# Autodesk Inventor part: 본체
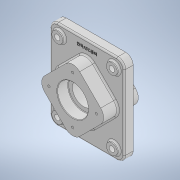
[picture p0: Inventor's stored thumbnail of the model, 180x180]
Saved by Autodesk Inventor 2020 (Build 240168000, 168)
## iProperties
Created: 2021-07
Part Number: 본체
Material: 일반
Document SubType Name: Modeling
Designer: Owner
Mass: 807.262 g
Surface Area: 966.427 cm^2
Volume: 807.262 cm^3
Density: 1 g/cm^3
Appearance: 기본값
Author: Owner
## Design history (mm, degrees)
sketch "스케치1"
  geometry: L1 (75, 90)-(-75, 90); L2 (-75, 90)-(-75, -90); L3 (-75, -90)-(75, -90); L4 (75, -90)-(75, 90); L5 (75, 90)-(-75, -90); L6 (-75, 90)-(75, -90); 1 further point
  constraints: 12 end point, 2 midpoint, 2 parallel, 1 horizontal, 1 perpendicular
  dimensions: "d0" = 150 distance of L3.end L2.end; "d1" = 180 distance of L2.end L1.end
extrude "돌출1" new body sketch "스케치1" stored distance "d2" = 18; taper "d3" = 0 deg
sketch "스케치2"
  geometry: L1 (0, -70.711)-(-70.711, 0); L2 (-70.711, 0)-(0, 70.711); L3 (0, 70.711)-(70.711, 0); L4 (70.711, 0)-(0, -70.711); L5 (0, -70.711)-(0, 70.711); L6 (-70.711, 0)-(70.711, 0); 2 further points
  constraints: 12 end point, 3 midpoint, 2 parallel, 1 horizontal alignment, 1 perpendicular, 1 vertical alignment
  dimensions: "d4" = 100 distance of L1.end L2.end
extrude "돌출2" join sketch "스케치2" distance "d5" = 29; taper "d6" = 0 deg
sketch "스케치3"
  geometry: L1 (0, 70.711)-(-70.711, 0) reference; L2 (70.711, 0)-(0, 70.711) reference; L3 (-70.711, 0)-(0, -70.711) reference; L4 (0, -70.711)-(70.711, 0) reference; L5 (-75, -90)-(75, -90) reference; L6 (75, -90)-(75, 90) reference; L7 (75, 90)-(-75, 90) reference; L8 (-75, 90)-(-75, -90) reference; 1 further point
extrude "돌출3" join sketch "스케치3" distance "d7" = 23; taper "d8" = 0 deg
fillet "모깎기1" dims "d9" = 20
fillet "모깎기2" dims "d10" = 20
sketch "스케치4"
  geometry: 2 further points
  constraints: 1 vertical alignment
  dimensions: "d11" = 48 distance of point (0, 0) point (0, 48)
hole "구멍1" sketch "스케치4" at (0, 48) diameter "d12" = 4.917; stored, may be unused: countersink angle "d16" = 90 deg, drill point angle "d18" = 118 deg; dims "d13" = 10, "d14" = 4, "d15" = 2, "d17" = 13
sketch "스케치5"
  geometry: C1 r 31 at (0, 0); 1 further point
  constraints: 1 centre point, 1 coincident
  dimensions: "d19" = 62 diameter of C1
extrude "돌출4" cut sketch "스케치5" distance "d20" = 22; taper "d21" = 0 deg
sketch "스케치6"
  geometry: C1 r 31 at (0, 0); 1 further point
  constraints: 1 centre point, 1 coincident
  dimensions: "d22" = 62 diameter of C1
extrude "돌출5" cut sketch "스케치6" distance "d23" = 22; taper "d24" = 0 deg
sketch "스케치7"
  geometry: C1 r 31 at (0, 0) reference; C2 r 22.5 at (0, 0); 1 further point
  constraints: 1 centre point, 1 coincident
  dimensions: "d25" = 45 diameter of C2
extrude "돌출6" cut sketch "스케치7" extent not by distance; stored distance "d26" = 22; taper "d27" = 0 deg
sketch "스케치8"
  geometry: 2 further points
  constraints: 1 vertical alignment
  dimensions: "d31" = 48 distance of point (0, 0) point (0, 48)
hole "구멍2" sketch "스케치8" at (0, 48) diameter "d32" = 4.917; stored, may be unused: countersink angle "d36" = 90 deg, drill point angle "d38" = 118 deg; dims "d33" = 10, "d34" = 4, "d35" = 2, "d37" = 13
fillet "모깎기3" dims "d42" = 15
sketch "스케치9"
  geometry: L1 (75, -75)-(75, 75) reference; L2 (60, 90)-(-60, 90) reference; L3 (-75, 75)-(-75, -75) reference; L4 (-60, -90)-(60, -90) reference; L5 (-14.142, -56.569)-(-56.569, -14.142) reference; L6 (-56.569, 14.142)-(-14.142, 56.569) reference; L7 (14.142, 56.569)-(56.569, 14.142) reference; L8 (56.569, -14.142)-(14.142, -56.569) reference; L9 (14.142, -56.569)-(56.569, -14.142) reference; L10 (56.569, 14.142)-(14.142, 56.569) reference; L11 (-14.142, 56.569)-(-56.569, 14.142) reference; L12 (-56.569, -14.142)-(-14.142, -56.569) reference; C1 r 2.458 at (-48, 0) reference; C2 r 2.458 at (0, -48) reference; C3 r 2.458 at (48, 0) reference; C4 r 2.458 at (0, 48) reference; C5 r 31 at (0, 0) reference; C6 r 11 at (-55, -70); C7 r 11 at (-55, 70); C8 r 11 at (55, -70); C9 r 11 at (55, 70); A1 r 15 centre (60, -75) between (60, -90) and (75, -75) reference; A2 r 15 centre (60, 75) between (75, 75) and (60, 90) reference; A3 r 15 centre (-60, 75) between (-60, 90) and (-75, 75) reference; A4 r 15 centre (-60, -75) between (-75, -75) and (-60, -90) reference; A5 r 20 centre (-42.426, 0) between (-56.569, 14.142) and (-56.569, -14.142) reference; A6 r 20 centre (0, 42.426) between (14.142, 56.569) and (-14.142, 56.569) reference; A7 r 20 centre (42.426, 0) between (56.569, -14.142) and (56.569, 14.142) reference; A8 r 20 centre (0, -42.426) between (-14.142, -56.569) and (14.142, -56.569) reference; A9 r 20 centre (0, -42.426) between (-14.142, -56.569) and (14.142, -56.569) reference; A10 r 20 centre (42.426, 0) between (56.569, -14.142) and (56.569, 14.142) reference; A11 r 20 centre (0, 42.426) between (14.142, 56.569) and (-14.142, 56.569) reference; A12 r 20 centre (-42.426, 0) between (-56.569, 14.142) and (-56.569, -14.142) reference; 1 further point
  constraints: 4 centre point
  dimensions: "d43" = 22 diameter of C6; "d44" = 22 diameter of C7; "d45" = 22 diameter of C8; "d46" = 22 diameter of C9; "d47" = 140 distance of C6.centre C7.centre; "d48" = 70 vertical distance of point (0, 0) C7.centre; "d49" = 110 distance of C8.centre C6.centre; "d50" = 55 horizontal distance of point (0, 0) C6.centre; "d51" = 110 distance of C9.centre C7.centre; "d52" = 55 horizontal distance of point (0, 0) C7.centre; "d53" = 140 distance of C8.centre C9.centre; "d54" = 70 vertical distance of point (0, 0) C9.centre
extrude "돌출7" join sketch "스케치9" distance "d55" = 5; taper "d56" = 0 deg
sketch "스케치10"
  geometry: C1 r 11 at (0, 0) reference; 2 further points
  constraints: 1 coincident
hole "구멍3" sketch "스케치10" at (0, 0) diameter "d57" = 11; stored, may be unused: countersink angle "d61" = 90 deg, drill point angle "d63" = 118 deg; dims "d58" = 10, "d59" = 4, "d60" = 2, "d62" = 13
fillet "모깎기4" dims "d64" = 1
chamfer "모따기1" distance "d65" = 1; stored, may be unused: second distance "d66" = 2, angle "d67" = 45 deg
fillet "모깎기6" dims "d69" = 3
sketch "스케치12"
  geometry: L1 (75, -75)-(75, 75) reference; L2 (60, 90)-(-60, 90) reference; L3 (-75, 75)-(-75, -75) reference; L4 (-60, -90)-(60, -90) reference; L5 (-14.142, -56.569)-(-56.569, -14.142) reference; L6 (-56.569, 14.142)-(-14.142, 56.569) reference; L7 (14.142, 56.569)-(56.569, 14.142) reference; L8 (56.569, -14.142)-(14.142, -56.569) reference; C1 r 14 at (55, -70) reference; C2 r 14 at (-55, 70) reference; C3 r 14 at (55, 70) reference; C4 r 14 at (-55, -70) reference; A1 r 15 centre (60, -75) between (60, -90) and (75, -75) reference; A2 r 15 centre (60, 75) between (75, 75) and (60, 90) reference; A3 r 15 centre (-60, 75) between (-60, 90) and (-75, 75) reference; A4 r 15 centre (-60, -75) between (-75, -75) and (-60, -90) reference; A5 r 20 centre (-42.426, 0) between (-56.569, 14.142) and (-56.569, -14.142) reference; A6 r 20 centre (0, 42.426) between (14.142, 56.569) and (-14.142, 56.569) reference; A7 r 20 centre (42.426, 0) between (56.569, -14.142) and (56.569, 14.142) reference; A8 r 20 centre (0, -42.426) between (-14.142, -56.569) and (14.142, -56.569) reference; 2 further points
  constraints: 1 vertical alignment, 1 other
  dimensions: "d70" = 15 distance from line of L2 point (0, 75)
feature "엠보싱1" sketch "스케치12" dims "d0" = 150, "d1" = 180, "d71" = 0.5, "d72" = 0
fillet "모깎기7" dims "d73" = 3
fillet "모깎기8" dims "d74" = 3
node "솔리드1"
pattern_circular "원형 패턴1" dims angle "d29" = 360 deg
pattern_circular "원형 패턴2" dims angle "d40" = 360 deg
mirror "미러2"
mirror "미러3"
node "투영된 루프1"
node "투영된 루프2"
node "투영된 루프3"
node "투영된 루프4"
feature "A9D066F2-1C7D-4E18-AEED-F7BC21143FA4" dims "d57" = 11, "d58" = 10, "d59" = 4, "d60" = 2, "d61" = 90 deg, "d62" = 13, "d63" = 118 deg
